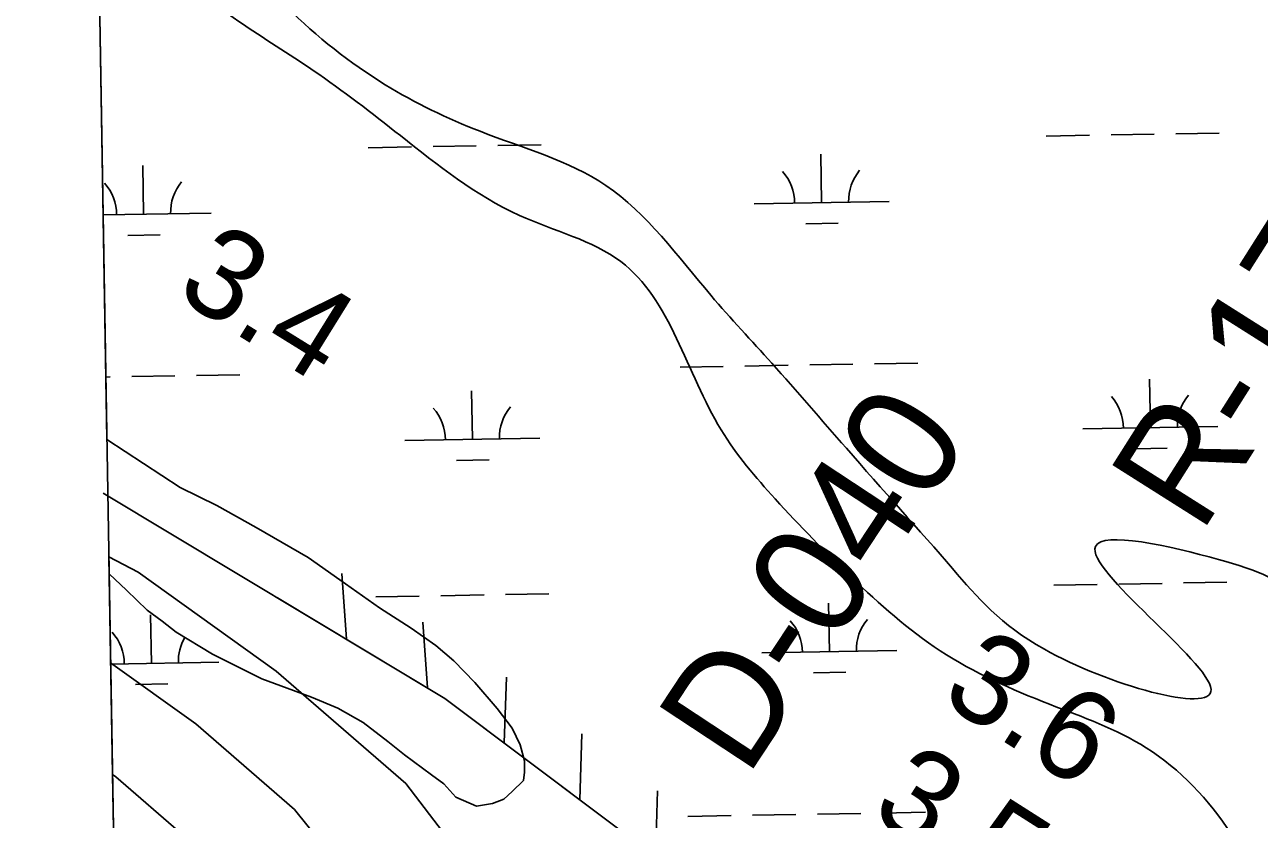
# Model space of a CAD drawing. Extents: x 3887375 to 3925618, y 296674 to 322633.
# Drawn here: x 3891343 to 3892257, y 316367 to 316956 of the extents above; entities that cross this region are included whole.
import ezdxf

# ---------------------------------------------------------------- set-up
doc = ezdxf.new("R2010")
doc.units = 0
for name, color, linetype in [('V-GRID-FRAM', 7, 'Continuous'), ('V-RIVR-RANG', 7, 'Continuous'), ('V-RIVR-RANG-IDEN', 7, 'Continuous'), ('V-RRAP-FSHR', 7, 'Continuous'), ('V-TOPO-DPTH', 7, 'Continuous'), ('V-TOPO-MINR', 7, 'Continuous'), ('V-TOPO-SHOR', 7, 'Continuous'), ('V-TOPO-WATR', 7, 'Continuous'), ('V-WETL-SWMP', 7, 'Continuous')]:
    doc.layers.add(name, color=color, linetype=linetype)

msp = doc.modelspace()

# ---------------------------------------------------------------- linework, layer by layer
at = {"layer": 'V-GRID-FRAM'}
msp.add_lwpolyline([(3891343.33, 320285.84), (3923192.81, 320832.52), (3923512.79, 302652.88), (3891647.44, 302105.93), (3891343.33, 320285.84)], dxfattribs=at)
at = {"layer": 'V-RRAP-FSHR'}
for p, q in [((3891581.39, 316500.52), (3891577.99, 316549.23)), ((3891641.38, 316464.45), (3891637.99, 316513.16)), ((3891698.21, 316423.7), (3891699.86, 316472.5)), ((3891754.17, 316381.64), (3891755.81, 316430.45)), ((3891810.13, 316339.59), (3891811.77, 316388.39))]:
    msp.add_line(p, q, dxfattribs=at)
for points in [[(3891401.41, 316608.72), (3891654.41, 316456.62), (3892169.8, 316069.29)], [(3891530.52, 316531.1), (3891654.41, 316456.62), (3891904.01, 316269.03)]]:
    msp.add_lwpolyline(points, dxfattribs=at)
at = {"layer": 'V-TOPO-DPTH'}
for p, q in [((3891405.62, 316561.67), (3891408.32, 316400.36)), ((3891408.32, 316400.36), (3891411.08, 316235.56))]:
    msp.add_line(p, q, dxfattribs=at)
for points in [[(3892270.22, 315782.9), (3891902.63, 316043.82), (3891889.44, 316054.31), (3891877.11, 316065.64), (3891866.08, 316078.24), (3891855.91, 316091.68), (3891625.32, 316393.62), (3891529.45, 316476.97), (3891427.39, 316550.28), (3891405.62, 316561.67)], [(3892574.45, 315521.57), (3892161.69, 315790), (3892107.32, 315825.19), (3892052.85, 315860.22), (3891998.22, 315895.01), (3891943.5, 315929.65), (3891849.6, 315988.79), (3891841.77, 315993.78), (3891833.98, 315998.81), (3891826.23, 316003.92), (3891818.52, 316009.09), (3891756.21, 316051.24), (3891723.89, 316074.54), (3891692.58, 316099.05), (3891662.79, 316125.39), (3891634.01, 316152.94), (3891460.78, 316355.12), (3891410.73, 316398.63), (3891408.32, 316400.36)], [(3891408.32, 316400.36), (3891410.73, 316398.63), (3891460.78, 316355.12), (3891634.01, 316152.94), (3891662.79, 316125.39), (3891692.58, 316099.05), (3891723.89, 316074.54), (3891756.21, 316051.24), (3891818.52, 316009.09), (3891826.23, 316003.92), (3891833.98, 315998.81), (3891841.77, 315993.78), (3891849.6, 315988.79), (3891943.5, 315929.65), (3891998.22, 315895.01), (3892052.85, 315860.22), (3892107.32, 315825.19), (3892161.69, 315790), (3892574.45, 315521.57)]]:
    msp.add_lwpolyline(points, dxfattribs=at)
at = {"layer": 'V-TOPO-MINR'}
for points in [[(3892571.04, 315538.71), (3891933.3, 315951.31), (3891917.98, 315961.18), (3891902.63, 315971), (3891887.24, 315980.75), (3891871.82, 315990.46), (3891845.51, 316006.94), (3891843.23, 316008.39), (3891840.97, 316009.87), (3891838.73, 316011.37), (3891836.51, 316012.9), (3891822.83, 316022.47), (3891814.18, 316029.2), (3891806.06, 316036.47), (3891798.72, 316044.53), (3891791.91, 316053.12), (3891737.06, 316130.14), (3891726.02, 316146.68), (3891543.05, 316374.37), (3891470.09, 316437.8), (3891406.94, 316483.17)], [(3892574.45, 315521.57), (3892161.69, 315790), (3892107.32, 315825.19), (3892052.85, 315860.22), (3891998.22, 315895.01), (3891943.5, 315929.65), (3891849.6, 315988.79), (3891841.77, 315993.78), (3891833.98, 315998.81), (3891826.23, 316003.92), (3891818.52, 316009.09), (3891756.21, 316051.24), (3891723.89, 316074.54), (3891692.58, 316099.05), (3891662.79, 316125.39), (3891634.01, 316152.94), (3891460.78, 316355.12), (3891410.73, 316398.63), (3891408.32, 316400.36)]]:
    msp.add_lwpolyline(points, dxfattribs=at)
at = {"layer": 'V-TOPO-SHOR'}
for points in [[(3891662.4, 316383.64), (3891677.62, 316376.97), (3891689.64, 316379), (3891697.91, 316382.21), (3891704.21, 316387.66), (3891712.55, 316395.97), (3891713.31, 316402.17), (3891713.22, 316410.39), (3891710.07, 316422.43), (3891704.05, 316434.74), (3891692.95, 316449.34), (3891676.59, 316468.47), (3891660.85, 316484.48), (3891647.7, 316496.01), (3891629.47, 316508.72), (3891605.94, 316523.74), (3891580.68, 316541.67), (3891553.22, 316560.97), (3891514.71, 316583.33), (3891485.42, 316599.55), (3891458.32, 316612.84), (3891404.17, 316648.55)], [(3891405.83, 316549.02), (3891418.73, 316536.85), (3891434.04, 316522.18), (3891445.02, 316514.01), (3891455.33, 316505.86), (3891482.39, 316489.45), (3891518.75, 316471.13), (3891537.52, 316464.4), (3891555.62, 316457.68), (3891575.04, 316449.39), (3891593.97, 316438.88), (3891612.18, 316424.83), (3891624.47, 316414.87), (3891644.44, 316400.13), (3891653.67, 316393.55), (3891662.4, 316383.64)]]:
    msp.add_lwpolyline(points, dxfattribs=at)
for points in [[(3892755.11, 317229.11), (3892764.03, 317201.54), (3892752.93, 317138.33), (3892727.56, 317081.16), (3892715.17, 316984.92), (3892723.33, 316924.2), (3892675.19, 316851.23), (3892597.33, 316817.88), (3892493.94, 316774.55), (3892429.58, 316737.05), (3892379.52, 316682.07), (3892392.36, 316548.98), (3892411.9, 316485.47), (3892366.55, 316440.08), (3892292.28, 316524.72), (3892226.91, 316559.6), (3892135.87, 316569.26), (3892221.4, 316463.39), (3892098.04, 316493.06), (3892030.15, 316552.84), (3891951.47, 316641.92), (3891896.37, 316704.94), (3891851.23, 316755.25), (3891773.42, 316836.6), (3891680.4, 316876.68), (3891610.21, 316911.23), (3891537.49, 316968.41), (3891487.81, 317017.45), (3891448.98, 317043.78), (3891406.69, 317064.93)], [(3891406.69, 317064.93), (3891440.04, 317012.88), (3891501.92, 316958.04), (3891556.85, 316921.78), (3891621.36, 316873.53), (3891709.52, 316814.44), (3891784.54, 316780.19), (3891858.77, 316655.67), (3891898.88, 316604.41), (3891955.54, 316546.26), (3892020.94, 316492), (3892101.94, 316452.38), (3892173.4, 316420.18), (3892236.09, 316356.54), (3892265.95, 316301.05), (3892313.89, 316188.46), (3892308.96, 316092.86), (3892292.04, 316050.56)]]:
    msp.add_spline(points, degree=3, dxfattribs=at)
at = {"layer": 'V-TOPO-WATR'}
msp.add_lwpolyline([(3892270.22, 315782.9), (3891902.63, 316043.82), (3891889.44, 316054.31), (3891877.11, 316065.64), (3891866.08, 316078.24), (3891855.91, 316091.68), (3891625.32, 316393.62), (3891529.45, 316476.97), (3891427.39, 316550.28), (3891405.62, 316561.67)], dxfattribs=at)
at = {"layer": 'V-WETL-SWMP'}
for p, q in [((3891404.17, 316648.55), (3891376.81, 318283.85)), ((3892099.43, 316873.18), (3892131.43, 316873.73)), ((3892147.43, 316874), (3892179.42, 316874.55)), ((3892195.42, 316874.83), (3892227.41, 316875.38)), ((3891597.6, 316864.57), (3891629.59, 316865.11)), ((3891645.59, 316865.39), (3891677.59, 316865.94)), ((3891693.58, 316866.21), (3891725.58, 316866.76)), ((3891933.19, 316823.89), (3891932.57, 316859.88)), ((3891431.36, 316815.28), (3891430.74, 316851.27)), ((3891883.2, 316823.03), (3891983.18, 316824.75)), ((3891401.39, 316814.76), (3891481.35, 316816.13)), ((3891921.46, 316808.25), (3891945.45, 316808.67)), ((3891419.62, 316799.64), (3891443.62, 316800.05)), ((3891828.42, 316702), (3891860.42, 316702.55)), ((3891876.42, 316702.83), (3891908.41, 316703.38)), ((3891924.41, 316703.65), (3891956.4, 316704.2)), ((3891972.4, 316704.47), (3892004.4, 316705.02)), ((3891403.4, 316694.71), (3891406.58, 316694.76)), ((3891422.57, 316695.04), (3891454.57, 316695.59)), ((3891470.57, 316695.86), (3891502.56, 316696.41)), ((3892176.56, 316657.23), (3892175.94, 316693.22)), ((3891674.72, 316648.61), (3891674.11, 316684.61)), ((3892126.57, 316656.37), (3892226.55, 316658.09)), ((3891458.32, 316612.85), (3891404.17, 316648.55)), ((3891624.73, 316647.76), (3891724.72, 316649.47)), ((3892164.82, 316641.59), (3892188.82, 316642.01)), ((3891662.99, 316632.98), (3891686.99, 316633.39)), ((3891485.42, 316599.55), (3891458.32, 316612.85)), ((3891514.71, 316583.33), (3891485.42, 316599.55)), ((3891553.22, 316560.97), (3891514.71, 316583.33)), ((3891580.68, 316541.67), (3891553.22, 316560.97)), ((3891409.9, 316306.1), (3891405.83, 316549.02)), ((3891405.83, 316549.02), (3891418.73, 316536.85)), ((3891418.73, 316536.85), (3891434.04, 316522.18)), ((3891605.94, 316523.74), (3891580.68, 316541.67)), ((3891699.29, 316533.59), (3891731.29, 316534.14)), ((3892105.14, 316540.55), (3892137.14, 316541.1)), ((3892153.14, 316541.38), (3892185.13, 316541.93)), ((3892201.13, 316542.2), (3892233.12, 316542.75)), ((3891603.31, 316531.94), (3891635.3, 316532.49)), ((3891651.3, 316532.76), (3891683.3, 316533.31)), ((3891938.9, 316491.26), (3891938.28, 316527.26)), ((3891434.04, 316522.18), (3891445.02, 316514.01)), ((3891437.07, 316482.65), (3891436.45, 316518.64)), ((3891629.47, 316508.72), (3891605.94, 316523.74)), ((3891445.02, 316514.01), (3891455.33, 316505.86)), ((3891647.7, 316496.01), (3891629.47, 316508.72)), ((3891455.33, 316505.86), (3891482.39, 316489.46)), ((3891482.39, 316489.46), (3891518.75, 316471.13)), ((3891660.85, 316484.48), (3891647.7, 316496.01)), ((3891888.91, 316490.41), (3891988.89, 316492.12)), ((3891406.95, 316482.13), (3891487.06, 316483.51)), ((3891676.59, 316468.47), (3891660.85, 316484.48)), ((3891518.75, 316471.13), (3891537.52, 316464.4)), ((3891927.17, 316475.63), (3891951.16, 316476.04)), ((3891425.33, 316467.01), (3891449.33, 316467.43)), ((3891537.52, 316464.4), (3891555.62, 316457.68)), ((3891692.95, 316449.34), (3891676.59, 316468.47)), ((3891555.62, 316457.68), (3891575.04, 316449.39)), ((3891575.04, 316449.39), (3891593.97, 316438.88)), ((3891704.05, 316434.74), (3891692.95, 316449.34)), ((3891593.97, 316438.88), (3891612.19, 316424.83)), ((3891710.07, 316422.43), (3891704.05, 316434.74)), ((3891612.19, 316424.83), (3891624.47, 316414.87)), ((3891713.22, 316410.39), (3891710.07, 316422.43)), ((3891624.47, 316414.87), (3891644.45, 316400.13)), ((3891713.31, 316402.17), (3891713.22, 316410.39)), ((3891644.45, 316400.13), (3891653.67, 316393.55)), ((3891712.55, 316395.97), (3891713.31, 316402.17)), ((3891653.67, 316393.55), (3891662.4, 316383.64)), ((3891704.21, 316387.66), (3891712.55, 316395.97)), ((3891662.4, 316383.64), (3891677.62, 316376.97)), ((3891677.62, 316376.97), (3891689.64, 316379)), ((3891689.64, 316379), (3891697.91, 316382.21)), ((3891697.91, 316382.21), (3891704.21, 316387.66)), ((3891834.13, 316369.38), (3891866.13, 316369.93)), ((3891882.12, 316370.2), (3891914.12, 316370.75)), ((3891930.12, 316371.02), (3891962.11, 316371.57)), ((3891978.11, 316371.85), (3892010.11, 316372.4))]:
    msp.add_line(p, q, dxfattribs=at)
for centre, start, end in [((3891877.95, 316823.42), 0.21154, 41.7552), ((3891988.42, 316825.31), 140.21154, 181.75519), ((3891376.11, 316814.8), 0.21154, 41.7552), ((3891486.58, 316816.7), 140.21154, 181.75519), ((3892231.78, 316658.65), 140.21154, 181.75519), ((3891619.48, 316648.14), 0.21154, 41.7552), ((3891729.95, 316650.04), 140.21154, 181.75519), ((3892121.32, 316656.75), 0.21154, 41.7552), ((3891883.66, 316490.79), 0.21154, 41.7552), ((3891994.13, 316492.69), 140.21154, 181.75519), ((3891381.82, 316482.18), 0.21154, 41.7552), ((3891492.29, 316484.07), 149.63328, 181.75519)]:
    msp.add_arc(centre, 35.25, start, end, dxfattribs=at)

# ---------------------------------------------------------------- texts
at = {"layer": 'V-RIVR-RANG'}
for s, rotation, p in [('3.4', 328.18833, (3891453.28, 316755.23)), ('3.6', 327.52833, (3892019.57, 316455.47)), ('3.5', 327.52833, (3891967.65, 316369.98))]:
    msp.add_text(s, height=67, rotation=rotation, dxfattribs=at).set_placement(p)
at = {"layer": 'V-RIVR-RANG-IDEN'}
for s, rotation, p in [('R-17.3', 57.66964, (3892213.66, 316577.43)), ('D-040', 56.58433, (3891877.74, 316397.29))]:
    msp.add_text(s, height=83, rotation=rotation, dxfattribs=at).set_placement(p)

doc.saveas('drawing.dxf')
